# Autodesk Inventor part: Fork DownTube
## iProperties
Shininess: 64.0
Length Units: 11272
Angle Units: 11279
Time Units: 11290
Mass Units: 11283
Length Display Precision: 3
Angle Display Precision: 2
Compacted: True
Part Number: Fork DownTube
Document SubType Name: Modeling
Created: 2005-03
Designer: Admin
Manufacturer: Standard
Standards Organization: Custom
Density: 1 g/cm^3
Density: 0.0
Volumn: 0.0
Area: 0.0
PropertySet Name: Model Information
Control State: 0
Master: False
Checked Out: False
Author: Admin
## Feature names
1. RevolutionFull1
2. ExtrusionMidplane1
3. ExtrusionMidplane2
4. PolarArray1 [Circular Pattern]
5. Fillet1
6. Fillet2
7. Fillet3
8. Fillet4
9. Shell1
